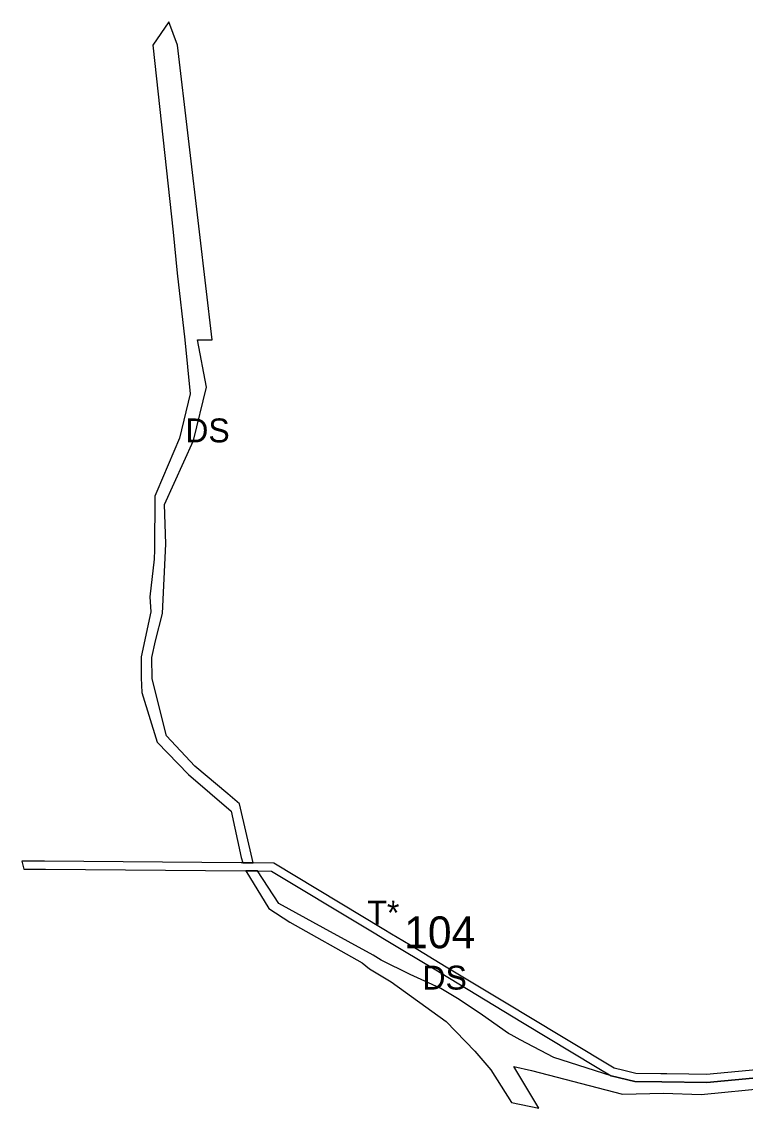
# Model space of a CAD drawing. Extents: x -477304 to -465641, y -1159113 to -1149285.
# Drawn here: x -476389.9 to -476117.4, y -1154804.9 to -1154395.5 of the extents above; entities that cross this region are included whole.
import ezdxf

# ---------------------------------------------------------------- set-up
doc = ezdxf.new("R2010")
doc.units = 0
for name, color, linetype in [('35', 7, 'Continuous'), ('4', 7, 'Continuous'), ('60', 7, 'Continuous')]:
    doc.layers.add(name, color=color, linetype=linetype)

msp = doc.modelspace()

# ---------------------------------------------------------------- linework, layer by layer
at = {"layer": '35'}
for p, q in [((-476334.48, -1154395.5), (-476340.47, -1154404.31)), ((-476340.47, -1154404.31), (-476332.87, -1154474.84)), ((-476332.87, -1154474.84), (-476331.29, -1154490.17)), ((-476318.18, -1154515.32), (-476322.97, -1154474.7)), ((-476331.29, -1154490.17), (-476328.52, -1154515.32)), ((-476328.52, -1154515.32), (-476326.49, -1154535.73)), ((-476320.29, -1154533.23), (-476323.69, -1154515.32)), ((-476323.69, -1154515.32), (-476318.18, -1154515.32)), ((-476326.49, -1154535.73), (-476330.45, -1154552.44)), ((-476339.78, -1154574.3), (-476339.93, -1154594.46)), ((-476339.93, -1154594.46), (-476340.04, -1154597.96)), ((-476340.04, -1154597.96), (-476341.61, -1154612.22)), ((-476341.61, -1154612.22), (-476341.33, -1154617.86)), ((-476340.79, -1154643.03), (-476340.89, -1154635.01)), ((-476344.86, -1154642.65), (-476344.6, -1154648.19)), ((-476335.36, -1154664.5), (-476340.79, -1154643.03)), ((-476344.6, -1154648.19), (-476338.83, -1154666.91)), ((-476324.65, -1154676.02), (-476335.36, -1154664.5)), ((-476338.83, -1154666.91), (-476327.06, -1154679.07)), ((-476312.26, -1154686.42), (-476324.65, -1154676.02)), ((-476327.06, -1154679.07), (-476310.98, -1154692.9)), ((-476307.85, -1154690.13), (-476312.26, -1154686.42)), ((-476310.98, -1154692.9), (-476307.26, -1154710.42)), ((-476302.74, -1154712.43), (-476307.85, -1154690.13)), ((-476307.26, -1154710.42), (-476306.65, -1154712.4)), ((-476305.5, -1154715.41), (-476296.82, -1154729.55)), ((-476293.04, -1154727.65), (-476301.06, -1154715.45)), ((-476261.71, -1154750.06), (-476258.96, -1154752.37)), ((-476254.52, -1154749.03), (-476257.57, -1154747.22)), ((-476243.58, -1154754.44), (-476254.52, -1154749.03)), ((-476258.96, -1154752.37), (-476250.7, -1154757.16)), ((-476236.66, -1154757.59), (-476243.58, -1154754.44)), ((-476232.02, -1154759.7), (-476236.66, -1154757.59)), ((-476225.11, -1154763.86), (-476232.02, -1154759.7)), ((-476216.38, -1154769.72), (-476225.11, -1154763.86)), ((-476206.56, -1154776.66), (-476216.38, -1154769.72)), ((-476205.57, -1154777.18), (-476206.56, -1154776.66)), ((-476202.13, -1154779.01), (-476205.57, -1154777.18)), ((-476195.17, -1154804.85), (-476204.6, -1154789.16)), ((-476204.6, -1154789.16), (-476197.83, -1154790.6)), ((-476197.83, -1154790.6), (-476163.64, -1154799.53)), ((-476163.64, -1154799.53), (-476148.23, -1154799.19)), ((-476148.23, -1154799.19), (-476133.97, -1154799.67)), ((-476133.97, -1154799.67), (-476108.48, -1154797.21)), ((-476205.44, -1154802.68), (-476195.17, -1154804.85))]:
    msp.add_line(p, q, dxfattribs=at)
for points in [[(-476322.97, -1154474.7), (-476331.19, -1154404.34), (-476334.48, -1154395.5)], [(-476336.08, -1154577.42), (-476325.15, -1154553.27), (-476320.29, -1154533.23)], [(-476330.45, -1154552.44), (-476338.98, -1154572.43), (-476339.78, -1154574.3)], [(-476336.89, -1154618.41), (-476335.56, -1154592.24), (-476336.08, -1154577.42)], [(-476341.33, -1154617.86), (-476344.91, -1154634.79), (-476344.86, -1154642.65)], [(-476340.89, -1154635.01), (-476339.52, -1154628.76), (-476336.89, -1154618.41)], [(-476306.65, -1154712.4), (-476303.54, -1154712.43), (-476302.74, -1154712.43)], [(-476301.06, -1154715.45), (-476301.51, -1154715.44), (-476305.5, -1154715.41)], [(-476296.82, -1154729.55), (-476288.93, -1154734.8), (-476261.71, -1154750.06)], [(-476257.57, -1154747.22), (-476276.4, -1154736.89), (-476293.04, -1154727.65)], [(-476250.7, -1154757.16), (-476230.03, -1154772.2), (-476219.25, -1154783.35)], [(-476167.92, -1154792.57), (-476189.46, -1154785.74), (-476202.13, -1154779.01)], [(-476219.25, -1154783.35), (-476213.26, -1154790.31), (-476205.44, -1154802.68)], [(-476148.76, -1154794.9), (-476158.97, -1154794.76), (-476167.92, -1154792.57)], [(-476103.83, -1154792.52), (-476103.86, -1154792.53), (-476131.8, -1154795.14), (-476148.76, -1154794.9)]]:
    msp.add_lwpolyline(points, dxfattribs=at)
at = {"layer": '4'}
for p, q in [((-476389.89, -1154711.73), (-476389.13, -1154714.73)), ((-476242.97, -1154743.82), (-476246.29, -1154741.82)), ((-476249.53, -1154743.37), (-476246.3, -1154745.32)), ((-476230.02, -1154751.63), (-476242.97, -1154743.82)), ((-476232.35, -1154753.73), (-476204.74, -1154770.37)), ((-476204.34, -1154767.11), (-476230.02, -1154751.63)), ((-476204.74, -1154770.37), (-476201.23, -1154772.49)), ((-476200.79, -1154769.25), (-476204.34, -1154767.11))]:
    msp.add_line(p, q, dxfattribs=at)
for points in [[(-476387.58, -1154711.75), (-476388.74, -1154711.74), (-476389.89, -1154711.73)], [(-476381.27, -1154711.8), (-476384.32, -1154711.77), (-476387.58, -1154711.75)], [(-476306.65, -1154712.4), (-476307.3, -1154712.4), (-476381.27, -1154711.8)], [(-476302.74, -1154712.43), (-476303.54, -1154712.43), (-476306.65, -1154712.4)], [(-476253.52, -1154737.46), (-476294.93, -1154712.5), (-476302.74, -1154712.43)], [(-476389.13, -1154714.73), (-476387.92, -1154714.74), (-476386.77, -1154714.75)], [(-476386.77, -1154714.75), (-476384.04, -1154714.78), (-476380.97, -1154714.8)], [(-476380.97, -1154714.8), (-476305.65, -1154715.41), (-476305.5, -1154715.41)], [(-476305.5, -1154715.41), (-476301.51, -1154715.44), (-476301.06, -1154715.45)], [(-476301.06, -1154715.45), (-476295.78, -1154715.49), (-476260.9, -1154736.52), (-476256.47, -1154739.19)], [(-476246.29, -1154741.82), (-476250.62, -1154739.21), (-476253.52, -1154737.46)], [(-476256.47, -1154739.19), (-476253.91, -1154740.73), (-476249.53, -1154743.37)], [(-476246.3, -1154745.32), (-476233.97, -1154752.75), (-476232.35, -1154753.73)], [(-476149.14, -1154791.9), (-476158.59, -1154791.77), (-476163.1, -1154790.66), (-476166.76, -1154789.77), (-476200.79, -1154769.25)], [(-476201.23, -1154772.49), (-476173.1, -1154789.45), (-476167.92, -1154792.57), (-476158.97, -1154794.76), (-476148.76, -1154794.9)], [(-476100.64, -1154791.48), (-476101.1, -1154789.74), (-476101.23, -1154789.27), (-476131.92, -1154792.14), (-476138.63, -1154792.04), (-476146.9, -1154791.93), (-476148.19, -1154791.91), (-476149.14, -1154791.9)], [(-476148.76, -1154794.9), (-476131.8, -1154795.14), (-476103.86, -1154792.53), (-476103.83, -1154792.52)]]:
    msp.add_lwpolyline(points, dxfattribs=at)

# ---------------------------------------------------------------- texts
at = {"layer": '35'}
for p in [(-476328.28, -1154553.97), (-476238.96, -1154760.13)]:
    msp.add_text('DS', height=9, dxfattribs=at).set_placement(p)
at = {"layer": '4'}
msp.add_text('T*', height=9, dxfattribs=at).set_placement((-476259.69, -1154735.67))
at = {"layer": '60'}
msp.add_text('104', height=12, dxfattribs=at).set_placement((-476245.85, -1154744.57))

doc.saveas('drawing.dxf')
